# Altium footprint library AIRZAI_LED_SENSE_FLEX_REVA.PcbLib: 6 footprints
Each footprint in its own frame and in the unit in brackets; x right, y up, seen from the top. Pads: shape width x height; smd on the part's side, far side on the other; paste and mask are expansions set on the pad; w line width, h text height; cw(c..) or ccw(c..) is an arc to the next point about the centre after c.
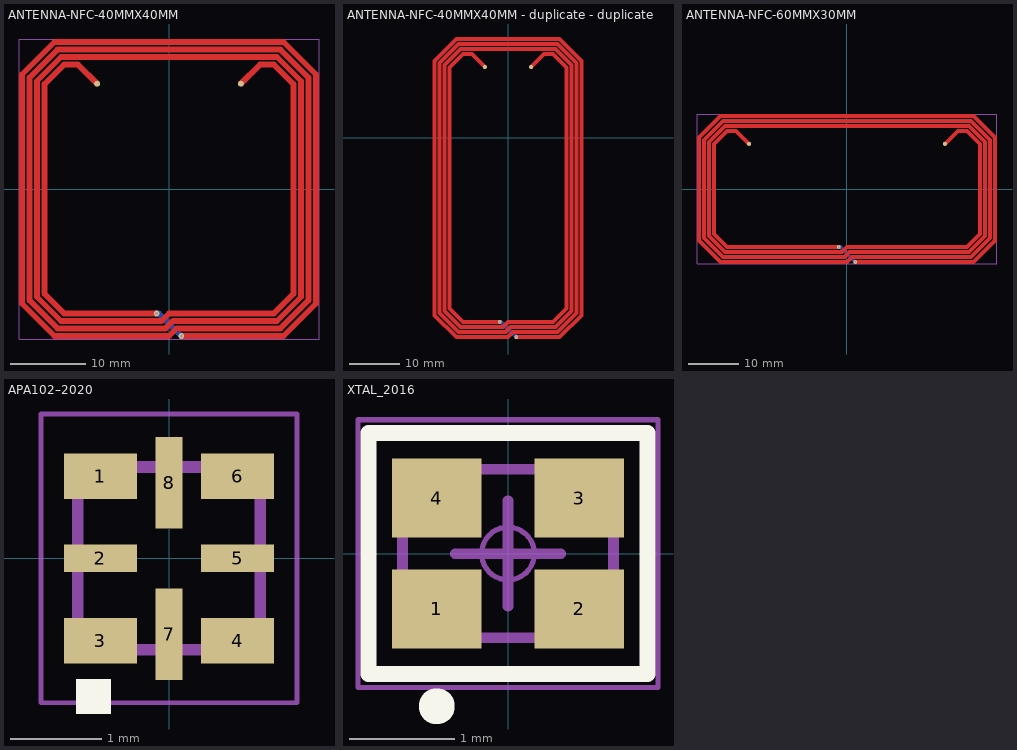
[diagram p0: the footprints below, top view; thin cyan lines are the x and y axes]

## ANTENNA-NFC-40MMX40MM [mil] "ANTENNA-ID2+10P-01"
pads (4):
  round 31.5 smd: 1(-377.5,552.5) 2(377.5,552.5)
  round 30 hole 15: 1(-65,-653.54) 2(65,-771.65)
Top Layer:
  lines w31.5: -377.5,552.5 -478.54,653.54 -550,653.54 -653.54,550 -653.54,-550 -550,-653.54 -65,-653.54 ; 65,-771.65 601.26,-771.65 771.65,-601.26 771.65,601.26 601.26,771.65 -601.26,771.65 -771.65,601.26 -771.65,-601.26 -601.26,-771.65 0,-771.65 39.37,-732.28 584.17,-732.28 732.28,-584.17 732.28,584.17 584.17,732.28 -584.17,732.28 -732.28,584.17 -732.28,-584.17 -584.17,-732.28 -19.37,-732.28 20,-692.91 567.09,-692.91 692.91,-567.09 692.91,567.09 567.09,692.91 -567.09,692.91 -692.91,567.09 -692.91,-567.09 -567.09,-692.91 -39.37,-692.91 0,-653.54 550,-653.54 653.54,-550 653.54,550 550,653.54 478.54,653.54 377.5,552.5
Bottom Layer:
  lines w31.5: -65,-653.54 -53.11,-653.54 65,-771.65
Mechanical 1:
  lines w3.94: -787.4,-787.4 -787.4,787.4 787.4,787.4 787.4,-787.4 -787.4,-787.4

## ANTENNA-NFC-40MMX40MM - duplicate - duplicate [mil] "ANTENNA-ID2+10P-01"
pads (4):
  round 31.5 smd: 1(-180.65,552.5) 1(180.65,552.5)
  round 30 hole 15: 1(-65,-1440.95) 2(65,-1559.05)
Top Layer:
  lines w31.5: -180.65,552.5 -281.69,653.54 -353.15,653.54 -456.69,550 -456.69,-1337.4 -353.15,-1440.95 -65,-1440.95 ; 65,-1559.05 404.41,-1559.05 574.8,-1388.66 574.8,601.26 404.41,771.65 -404.41,771.65 -574.8,601.26 -574.8,-1388.66 -404.41,-1559.06 0,-1559.06 39.37,-1519.69 387.32,-1519.69 535.43,-1371.57 535.43,584.17 387.32,732.28 -387.32,732.28 -535.43,584.17 -535.43,-1371.57 -387.32,-1519.69 -19.37,-1519.69 20,-1480.32 370.24,-1480.32 496.06,-1354.49 496.06,567.09 370.24,692.91 -370.24,692.91 -496.06,567.09 -496.06,-1354.49 -370.24,-1480.32 -39.37,-1480.32 0,-1440.95 353.15,-1440.95 456.69,-1337.4 456.69,550 353.15,653.54 281.69,653.54 180.65,552.5
Bottom Layer:
  lines w31.5: -65,-1440.95 -53.11,-1440.95 65,-1559.05

## ANTENNA-NFC-60MMX30MM [mil] "ANTENNA-ID2+10P-01"
pads (4):
  round 31.5 smd paste-31.5: 1(-771.2,355.65) 2(771.2,355.65)
  round 30 hole 15: 1(-65,-456.69) 2(65,-574.8)
Top Layer:
  lines w31.5: -771.2,355.65 -872.24,456.69 -943.7,456.69 -1047.24,353.15 -1047.24,-353.15 -943.7,-456.69 -65,-456.69 ; 65,-574.8 994.96,-574.8 1165.35,-404.41 1165.35,404.41 994.96,574.8 -994.96,574.8 -1165.35,404.41 -1165.35,-404.41 -994.96,-574.8 0,-574.8 39.37,-535.43 977.87,-535.43 1125.98,-387.32 1125.98,387.32 977.87,535.43 -977.87,535.43 -1125.98,387.32 -1125.98,-387.32 -977.87,-535.43 -19.37,-535.43 20,-496.06 960.79,-496.06 1086.61,-370.24 1086.61,370.24 960.79,496.06 -960.79,496.06 -1086.61,370.24 -1086.61,-370.24 -960.79,-496.06 -39.37,-496.06 0,-456.69 943.7,-456.69 1047.24,-353.15 1047.24,353.15 943.7,456.69 872.24,456.69 771.2,355.65
Bottom Layer:
  lines w31.5: -65,-456.69 -53.11,-456.69 65,-574.8
Mechanical 1:
  lines w3.94: -1181.1,-590.55 -1181.1,590.55 ; 1181.1,-590.55 1181.1,590.55
  lines w5: -1181.1,-590.55 1181.1,-590.55 ; -1181.1,590.55 1181.1,590.55

## APA102–2020 [mm]
pads (8):
  rect 0.8x0.5 smd: 1(-0.75,0.9) 3(-0.75,-0.9) 4(0.75,-0.9) 6(0.75,0.9)
  rect 0.8x0.3 smd: 2(-0.75,0) 5(0.75,0)
  rect 0.3x1 smd: 7(0,-0.83) 8(0,0.83)
Top Overlay:
  rectangle: -1.016,-1.702 -0.635,-1.321
Mechanical 13 (Mech13):
  lines w0.127: -1,-1 1,-1 1,1 -1,1 -1,-1
Mechanical 16:
  lines w0.05: -1.4,-1.58 1.4,-1.58 1.4,1.58 -1.4,1.58 -1.4,-1.58
3D body: height 0.94, standoff 0, extent -0.698,0.254 -0.317,0.762
3D body: height 0.94, standoff 0, extent -0.19,0.254 0.191,0.762
3D body: height 0.94, standoff 0, extent 0.318,0.254 0.699,0.762
3D body: height 0.91, standoff 0, extent -1,-1 1,1

## PCBComponent_1 [mm]

## XTAL_2016 [mm] "2.00mm x 1.60mm"
height 1
pads (4):
  rect 0.85x0.75 smd: 1(-0.675,-0.525) 2(0.675,-0.525) 3(0.675,0.525) 4(-0.675,0.525)
Top Overlay:
  circle w0.3: c-0.675,-1.448 r0.02
  lines w0.152: -1.321,-1.143 -1.321,1.143 1.321,1.143 1.321,-1.143 -1.321,-1.143
Mechanical 1:
  text ".Designator" at -0.508,-0.229 h0.51
Mechanical 13 (Mech13):
  lines w0.1: -1,-0.8 1,-0.8 ; -1,0.8 1,0.8
  lines w0.102: -1,-0.8 -1,0.8 ; 1,-0.8 1,0.8
Mechanical 15:
  circle w0.05: c0,0 r0.25
  lines w0.05: -1.422,-1.27 1.422,-1.27 1.422,0.686 1.422,1.27 -1.422,1.27 -1.422,-1.27
  lines w0.1: -0.5,0 0.5,0 ; 0,-0.5 0,0.5
3D body "User Library-XRCGB27M000F2P00R0.STEP": height 0.65, standoff 0, extent -1,-0.813 1,0.787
